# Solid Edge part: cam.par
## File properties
Author: Robert a Rhodes jr
Template: normal.par
Last saved by: Cadcim
Revision: 3
Application: Solid Edge
Accuracy: 0.99
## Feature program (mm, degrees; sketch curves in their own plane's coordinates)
sketch for "unnamed Protrusion 1" plane through (0, 0, 0) normal (0, -1, 0) x-axis (1, 0, 0)
  line (-48.7213, 38.3333) -> (-48.7213, 0)
  line (-48.7213, 0) -> (73.8435, 0)
  line (73.8435, 0) -> (73.8435, -9.0712)
  line (73.8435, -9.0712) -> (-55.4516, -9.0712)
  line (-55.4516, -9.0712) -> (-55.4516, 38.3333)
  line (-55.4516, 38.3333) -> (-48.7213, 38.3333)
extrude "unnamed Protrusion 1" add finite 37.8 along -normal
sketch for "ExtrudedCutout_1" plane through (-48.7213, 18.9, 19.1666) normal (1, 0, 0) x-axis (0, 1, 0)
  line (-5.0674, -0.2952) -> (-5.0674, 8.2652)
  line (-5.0674, 8.2652) -> (3.6898, 8.2652)
  line (3.6898, 8.2652) -> (3.6898, -0.2952)
  line (3.6898, -0.2952) -> (-5.0674, -0.2952)
extrude "ExtrudedCutout_1" cut finite 123.95 along -normal
sketch for "Hole_1" plane through (12.5611, 18.9, 0) normal (0, 0, 1) x-axis (0, 1, 0)
  hole centre (0.7865, -41.5278) bore radius 3.5
hole "Hole_1" diameter 7 through
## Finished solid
Body 1: solid body, 13 faces, 32 edges, 20 vertices.
  Faces by surface: plane 12, cylinder 1
  Edges by curve: line 30, circle 2
Bounding box of the edges (mm): 129.295 x 37.800 x 47.404, from (-55.4516, 0, -9.0712) to (73.8435, 37.8, 38.3333).
Cylindrical faces by radius (mm): R3.5 x1
Planar faces by outward normal: +x 2, +y 2, +z 3, -x 1, -y 2, -z 2
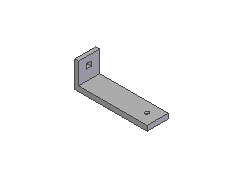
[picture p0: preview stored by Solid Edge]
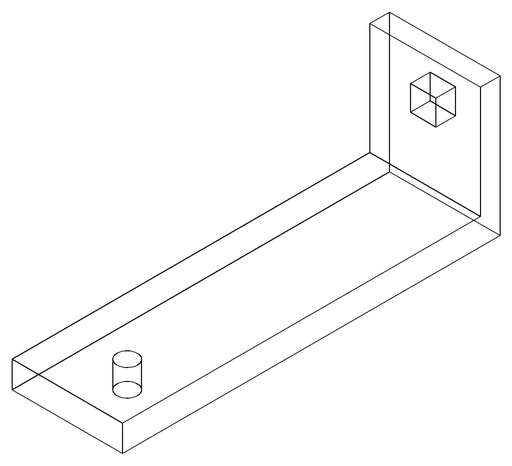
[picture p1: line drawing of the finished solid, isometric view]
